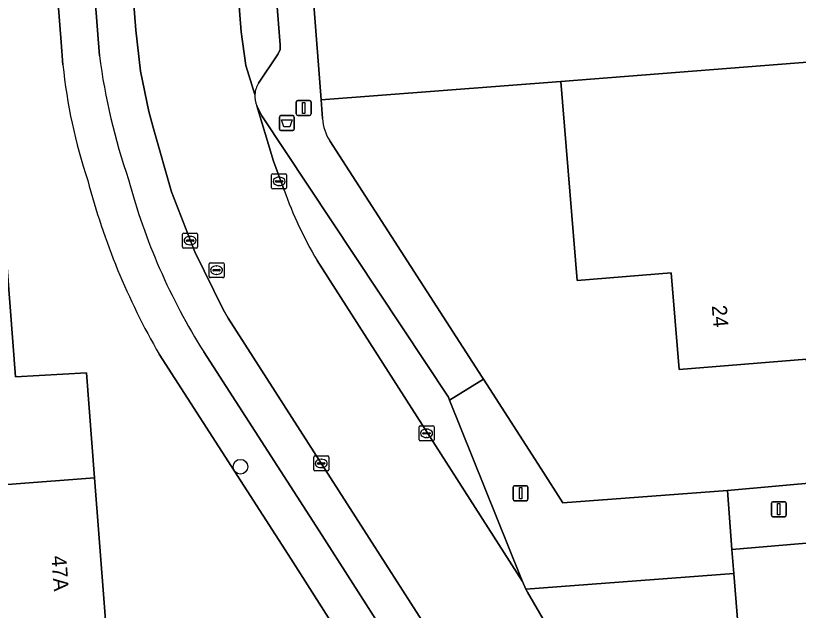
# Model space of a CAD drawing. Extents: x 157793 to 159380, y 380877 to 382313.
# Drawn here: x 158100.7 to 158152.9, y 381310.4 to 381350.1 of the extents above; entities that cross this region are included whole.
import ezdxf

# ---------------------------------------------------------------- set-up
doc = ezdxf.new("R2010")
doc.units = 0
for name, color, linetype in [('IMGEO_Afvalbak', 7, 'Continuous'), ('IMGEO_Boom', 7, 'Continuous'), ('IMGEO_Erf', 7, 'Continuous'), ('IMGEO_Kolk', 7, 'Continuous'), ('IMGEO_Lichtmast', 7, 'Continuous'), ('IMGEO_OVBaan_gesloten', 7, 'Continuous'), ('IMGEO_Pand', 7, 'Continuous'), ('IMGEO_Pand_nummerreeks', 7, 'Continuous'), ('IMGEO_Parkeervlak_open', 7, 'Continuous'), ('IMGEO_Rijbaan_lokaal_gesloten', 7, 'Continuous'), ('IMGEO_Rioolput', 7, 'Continuous'), ('IMGEO_Voetpad_open', 7, 'Continuous')]:
    doc.layers.add(name, color=color, linetype=linetype)

msp = doc.modelspace()

# ---------------------------------------------------------------- linework, layer by layer
at = {"layer": 'IMGEO_Afvalbak'}
for p, q in [((158118.269, 381342.493), (158118.269, 381343.293)), ((158118.269, 381343.293), (158118.269, 381342.493)), ((158118.369, 381343.393), (158119.159, 381343.393)), ((158119.159, 381343.393), (158118.369, 381343.393)), ((158119.259, 381343.293), (158119.259, 381342.493)), ((158119.259, 381342.493), (158119.259, 381343.293)), ((158119.159, 381342.393), (158118.369, 381342.393)), ((158118.369, 381342.393), (158119.159, 381342.393))]:
    msp.add_line(p, q, dxfattribs=at)
msp.add_lwpolyline([(158118.412, 381343.107), (158119.116, 381343.107), (158118.967, 381342.637), (158118.561, 381342.637), (158118.412, 381343.107)], dxfattribs=at)
for centre, start, end in [((158118.369, 381343.293), 90, 180), ((158118.369, 381343.293), 90, 180), ((158119.159, 381343.293), 0, 90), ((158119.159, 381343.293), 360, 90), ((158118.369, 381342.493), 180, 270), ((158118.369, 381342.493), 180, 270), ((158119.159, 381342.493), 270, 0), ((158119.159, 381342.493), 270, 0)]:
    msp.add_arc(centre, 0.1, start, end, dxfattribs=at)
at = {"layer": 'IMGEO_Boom'}
msp.add_circle((158115.672, 381319.964), 0.489, dxfattribs=at)
at = {"layer": 'IMGEO_Erf'}
for points in [[(158103.822, 381346.786), (158103.707, 381348.29), (158103.389, 381352.302), (158102.422, 381364.933), (158097.658, 381364.508), (158099.152, 381345.233), (158100.644, 381325.971), (158105.401, 381326.235), (158105.933, 381319.226), (158106.894, 381306.557), (158066.782, 381303.502), (158066.401, 381308.488), (158065.817, 381316.143), (158063.805, 381342.495), (158062.333, 381361.766), (158060.82, 381381.584), (158095.929, 381384.264), (158100.914, 381384.645), (158100.309, 381392.192)], [(158137.068, 381345.666), (158121.052, 381344.444), (158121.148, 381343.196)], [(158121.637, 381341.71), (158131.815, 381325.934), (158131.903, 381325.796), (158135.738, 381319.823), (158137.196, 381317.545), (158148.179, 381318.378), (158174.322, 381320.744), (158173.998, 381324.728), (158153.786, 381323.086), (158153.466, 381327.148), (158144.954, 381326.456), (158144.428, 381332.904), (158138.148, 381332.392), (158137.068, 381345.666)], [(158136.484, 381250), (158135.122, 381267.156), (158134.745, 381271.897), (158134.324, 381276.911), (158133.427, 381288.599), (158128.577, 381288.152), (158127.803, 381297.075), (158127.997, 381297.125), (158126.787, 381301.809), (158126.593, 381301.759), (158125.087, 381304.314), (158119.05, 381313.79), (158110.244, 381327.475)]]:
    msp.add_lwpolyline(points, dxfattribs=at)
for centre, radius, start, end in [((158138.842, 381350.248), 35.191, 185.645, 198.5212), ((158124.149, 381343.36), 3.006, 183.1301, 213.2997), ((158150.956, 381351.003), 47.022, 194.7024, 210.0241)]:
    msp.add_arc(centre, radius, start, end, dxfattribs=at)
at = {"layer": 'IMGEO_Kolk'}
for p, q in [((158117.753, 381338.58), (158117.753, 381339.432)), ((158117.828, 381339.506), (158118.68, 381339.506)), ((158118.241, 381339.286), (158118.266, 381339.286)), ((158118.754, 381339.432), (158118.754, 381338.58)), ((158118.012, 381339), (158118.012, 381339.012)), ((158118.45, 381338.963), (158118.052, 381338.963)), ((158118.055, 381339.049), (158118.453, 381339.049)), ((158118.264, 381338.726), (158118.239, 381338.726)), ((158118.496, 381339.012), (158118.496, 381339)), ((158118.68, 381338.506), (158117.828, 381338.506)), ((158111.808, 381334.628), (158111.808, 381335.48)), ((158111.883, 381335.554), (158112.735, 381335.554)), ((158112.809, 381335.48), (158112.809, 381334.628)), ((158112.067, 381335.048), (158112.067, 381335.06)), ((158112.505, 381335.011), (158112.107, 381335.011)), ((158112.11, 381335.097), (158112.508, 381335.097)), ((158112.296, 381335.334), (158112.321, 381335.334)), ((158112.551, 381335.06), (158112.551, 381335.048)), ((158112.735, 381334.554), (158111.883, 381334.554)), ((158112.319, 381334.774), (158112.294, 381334.774)), ((158127.592, 381321.767), (158127.592, 381322.619)), ((158127.667, 381322.693), (158128.519, 381322.693)), ((158128.08, 381322.473), (158128.105, 381322.473)), ((158128.593, 381322.619), (158128.593, 381321.767)), ((158127.851, 381322.187), (158127.851, 381322.199)), ((158128.289, 381322.15), (158127.891, 381322.15)), ((158127.894, 381322.236), (158128.292, 381322.236)), ((158128.103, 381321.913), (158128.078, 381321.913)), ((158128.335, 381322.199), (158128.335, 381322.187)), ((158128.519, 381321.693), (158127.667, 381321.693)), ((158120.562, 381319.759), (158120.562, 381320.611)), ((158120.637, 381320.685), (158121.489, 381320.685)), ((158121.05, 381320.465), (158121.075, 381320.465)), ((158121.563, 381320.611), (158121.563, 381319.759)), ((158120.821, 381320.179), (158120.821, 381320.191)), ((158121.259, 381320.142), (158120.861, 381320.142)), ((158120.864, 381320.228), (158121.262, 381320.228)), ((158121.073, 381319.905), (158121.048, 381319.905)), ((158121.305, 381320.191), (158121.305, 381320.179)), ((158121.489, 381319.685), (158120.637, 381319.685))]:
    msp.add_line(p, q, dxfattribs=at)
for points in [[(158117.753, 381338.58), (158117.753, 381339.432)], [(158117.828, 381339.506), (158118.68, 381339.506)], [(158118.754, 381339.432), (158118.754, 381338.58)], [(158118.68, 381338.506), (158117.828, 381338.506)], [(158111.808, 381334.628), (158111.808, 381335.48)], [(158111.883, 381335.554), (158112.735, 381335.554)], [(158112.809, 381335.48), (158112.809, 381334.628)], [(158112.735, 381334.554), (158111.883, 381334.554)], [(158127.592, 381321.767), (158127.592, 381322.619)], [(158127.667, 381322.693), (158128.519, 381322.693)], [(158128.593, 381322.619), (158128.593, 381321.767)], [(158128.519, 381321.693), (158127.667, 381321.693)], [(158120.562, 381319.759), (158120.562, 381320.611)], [(158120.637, 381320.685), (158121.489, 381320.685)], [(158121.563, 381320.611), (158121.563, 381319.759)], [(158121.489, 381319.685), (158120.637, 381319.685)]]:
    msp.add_lwpolyline(points, dxfattribs=at)
for centre, radius, start, end in [((158117.83, 381339.43), 0.0765, 91.552, 178.448), ((158117.83, 381339.43), 0.0765, 91.552, 178.448), ((158118.678, 381339.43), 0.0765, 1.552, 88.448), ((158118.678, 381339.43), 0.0765, 1.552, 88.448), ((158117.83, 381338.582), 0.0765, 181.552, 268.448), ((158117.83, 381338.582), 0.0765, 181.552, 268.448), ((158118.052, 381339.009), 0.0403, 85.8775, 175.7526), ((158118.049, 381338.999), 0.0366, 178.938, 274.7102), ((158118.453, 381339.006), 0.043, 264.8664, 352.4533), ((158118.457, 381339.011), 0.0386, 1.7309, 96.639), ((158118.678, 381338.582), 0.0765, 271.552, 358.448), ((158118.678, 381338.582), 0.0765, 271.552, 358.448), ((158111.885, 381335.478), 0.0765, 91.552, 178.448), ((158111.885, 381335.478), 0.0765, 91.552, 178.448), ((158112.733, 381335.478), 0.0765, 1.552, 88.448), ((158112.733, 381335.478), 0.0765, 1.552, 88.448), ((158112.107, 381335.057), 0.0403, 85.8775, 175.7526), ((158112.104, 381335.047), 0.0366, 178.938, 274.7102), ((158112.508, 381335.054), 0.043, 264.8664, 352.4533), ((158112.512, 381335.059), 0.0386, 1.7309, 96.639), ((158111.885, 381334.63), 0.0765, 181.552, 268.448), ((158111.885, 381334.63), 0.0765, 181.552, 268.448), ((158112.733, 381334.63), 0.0765, 271.552, 358.448), ((158112.733, 381334.63), 0.0765, 271.552, 358.448), ((158127.669, 381322.617), 0.0765, 91.552, 178.448), ((158127.669, 381322.617), 0.0765, 91.552, 178.448), ((158128.517, 381322.617), 0.0765, 1.552, 88.448), ((158128.517, 381322.617), 0.0765, 1.552, 88.448), ((158127.891, 381322.196), 0.0403, 85.8775, 175.7526), ((158127.888, 381322.186), 0.0366, 178.938, 274.7102), ((158128.292, 381322.193), 0.043, 264.8664, 352.4533), ((158128.296, 381322.198), 0.0386, 1.7309, 96.639), ((158127.669, 381321.769), 0.0765, 181.552, 268.448), ((158127.669, 381321.769), 0.0765, 181.552, 268.448), ((158128.517, 381321.769), 0.0765, 271.552, 358.448), ((158128.517, 381321.769), 0.0765, 271.552, 358.448), ((158120.639, 381320.609), 0.0765, 91.552, 178.448), ((158120.639, 381320.609), 0.0765, 91.552, 178.448), ((158121.487, 381320.609), 0.0765, 1.552, 88.448), ((158121.487, 381320.609), 0.0765, 1.552, 88.448), ((158120.639, 381319.761), 0.0765, 181.552, 268.448), ((158120.639, 381319.761), 0.0765, 181.552, 268.448), ((158120.861, 381320.188), 0.0403, 85.8775, 175.7526), ((158120.858, 381320.178), 0.0366, 178.938, 274.7102), ((158121.262, 381320.185), 0.043, 264.8664, 352.4533), ((158121.266, 381320.19), 0.0386, 1.7309, 96.639), ((158121.487, 381319.761), 0.0765, 271.552, 358.448), ((158121.487, 381319.761), 0.0765, 271.552, 358.448)]:
    msp.add_arc(centre, radius, start, end, dxfattribs=at)
for centre, major_axis, ratio, start_param, end_param in [((158118.24, 381339.006), (-0.387, 0.002), 0.722429, 4.712389, 7.853982), ((158118.265, 381339.006), (-0.39, 0.002), 0.717154, 1.570796, 4.712389), ((158112.295, 381335.054), (-0.387, 0.002), 0.722429, 4.712389, 7.853982), ((158112.32, 381335.054), (-0.39, 0.002), 0.717154, 1.570796, 4.712389), ((158128.079, 381322.193), (-0.387, 0.002), 0.722429, 4.712389, 7.853982), ((158128.104, 381322.193), (-0.39, 0.002), 0.717154, 1.570796, 4.712389), ((158121.049, 381320.185), (-0.387, 0.002), 0.722429, 4.712389, 7.853982), ((158121.074, 381320.185), (-0.39, 0.002), 0.717154, 1.570796, 4.712389)]:
    msp.add_ellipse(centre, major_axis=major_axis, ratio=ratio, start_param=start_param, end_param=end_param, dxfattribs=at)
at = {"layer": 'IMGEO_Lichtmast'}
for p, q in [((158119.395, 381343.503), (158119.395, 381344.303)), ((158119.395, 381344.303), (158119.395, 381343.503)), ((158119.495, 381344.403), (158120.285, 381344.403)), ((158120.285, 381344.403), (158119.495, 381344.403)), ((158120.385, 381344.303), (158120.385, 381343.503)), ((158120.385, 381343.503), (158120.385, 381344.303)), ((158120.285, 381343.403), (158119.495, 381343.403)), ((158119.495, 381343.403), (158120.285, 381343.403)), ((158133.975, 381318.693), (158134.765, 381318.693)), ((158134.765, 381318.693), (158133.975, 381318.693)), ((158133.875, 381317.793), (158133.875, 381318.593)), ((158133.875, 381318.593), (158133.875, 381317.793)), ((158134.865, 381318.593), (158134.865, 381317.793)), ((158134.865, 381317.793), (158134.865, 381318.593)), ((158134.765, 381317.693), (158133.975, 381317.693)), ((158133.975, 381317.693), (158134.765, 381317.693)), ((158151.115, 381316.726), (158151.115, 381317.526)), ((158151.115, 381317.526), (158151.115, 381316.726)), ((158151.215, 381317.626), (158152.005, 381317.626)), ((158152.005, 381317.626), (158151.215, 381317.626)), ((158152.105, 381317.526), (158152.105, 381316.726)), ((158152.105, 381316.726), (158152.105, 381317.526)), ((158152.005, 381316.626), (158151.215, 381316.626)), ((158151.215, 381316.626), (158152.005, 381316.626))]:
    msp.add_line(p, q, dxfattribs=at)
for points in [[(158119.815, 381344.278), (158119.965, 381344.278), (158119.965, 381343.528), (158119.815, 381343.528), (158119.815, 381344.278)], [(158134.295, 381318.568), (158134.445, 381318.568), (158134.445, 381317.818), (158134.295, 381317.818), (158134.295, 381318.568)], [(158151.535, 381317.501), (158151.685, 381317.501), (158151.685, 381316.751), (158151.535, 381316.751), (158151.535, 381317.501)]]:
    msp.add_lwpolyline(points, dxfattribs=at)
for centre, start, end in [((158119.495, 381344.303), 90, 180), ((158119.495, 381344.303), 90, 180), ((158120.285, 381344.303), 0, 90), ((158120.285, 381344.303), 360, 90), ((158119.495, 381343.503), 180, 270), ((158119.495, 381343.503), 180, 270), ((158120.285, 381343.503), 270, 0), ((158120.285, 381343.503), 270, 0), ((158133.975, 381318.593), 90, 180), ((158133.975, 381318.593), 90, 180), ((158134.765, 381318.593), 0, 90), ((158134.765, 381318.593), 360, 90), ((158133.975, 381317.793), 180, 270), ((158133.975, 381317.793), 180, 270), ((158134.765, 381317.793), 270, 0), ((158134.765, 381317.793), 270, 0), ((158151.215, 381317.526), 90, 180), ((158151.215, 381317.526), 90, 180), ((158152.005, 381317.526), 0, 90), ((158152.005, 381317.526), 360, 90), ((158151.215, 381316.726), 180, 270), ((158151.215, 381316.726), 180, 270), ((158152.005, 381316.726), 270, 0), ((158152.005, 381316.726), 270, 0)]:
    msp.add_arc(centre, 0.1, start, end, dxfattribs=at)
at = {"layer": 'IMGEO_OVBaan_gesloten'}
for points in [[(158129.628, 381324.416), (158129.552, 381324.607), (158117.104, 381343.377), (158116.771, 381344.039), (158117.878, 381340.348), (158118.578, 381338.424)], [(158120.787, 381333.732), (158134.501, 381312.302), (158134.337, 381312.678), (158129.628, 381324.416)]]:
    msp.add_lwpolyline(points, dxfattribs=at)
msp.add_arc((158144.688, 381347.851), 27.76, 199.8514, 210.5709, dxfattribs=at)
at = {"layer": 'IMGEO_Pand'}
for points in [[(158137.068, 381345.666), (158156.069, 381347.169), (158156.049, 381347.419), (158154.395, 381367.776), (158124.465, 381365.343), (158119.481, 381364.938), (158121.052, 381344.444)], [(158137.068, 381345.666), (158138.148, 381332.392), (158144.428, 381332.904), (158144.954, 381326.456), (158153.466, 381327.148), (158153.786, 381323.086), (158173.998, 381324.728), (158174.322, 381320.744), (158181.702, 381321.344), (158181.297, 381326.328), (158179.429, 381349.319), (158156.049, 381347.419), (158156.069, 381347.169)], [(158065.817, 381316.143), (158105.933, 381319.226), (158105.401, 381326.235), (158100.644, 381325.971), (158099.152, 381345.233), (158063.805, 381342.495)], [(158065.817, 381316.143), (158066.401, 381308.488), (158066.782, 381303.502), (158106.894, 381306.557), (158105.933, 381319.226)], [(158166.317, 381315.953), (158159.212, 381315.351), (158148.478, 381314.442), (158148.612, 381312.832), (158148.658, 381312.275), (158149.209, 381305.365), (158149.969, 381295.114), (158150.013, 381294.53), (158159.691, 381295.356), (158160.857, 381295.455), (158167.979, 381296.063)]]:
    msp.add_lwpolyline(points, close=True, dxfattribs=at)
at = {"layer": 'IMGEO_Parkeervlak_open'}
for points in [[(158068.546, 381497.113), (158089.726, 381454.684), (158103.399, 381426.613), (158104.154, 381425.047), (158107.132, 381417.89), (158109.46, 381410.496), (158111.117, 381402.923), (158112.092, 381395.233), (158115.709, 381348.982), (158116.021, 381346.737), (158116.632, 381344.813)], [(158133.891, 381298.949), (158130.692, 381305.062), (158129.631, 381306.832), (158114.85, 381329.868), (158114.523, 381330.452), (158112.621, 381334.306), (158111.071, 381338.314), (158109.885, 381342.445), (158109.545, 381343.679), (158108.99, 381346.367), (158108.678, 381349.094), (158105.079, 381395.169), (158104.129, 381402.425), (158102.534, 381409.567), (158100.308, 381416.538), (158097.468, 381423.282), (158097, 381424.252), (158084.358, 381449.773), (158063.323, 381491.963)], [(158101.929, 381399.96), (158102.313, 381397.022), (158102.595, 381394.475), (158103.917, 381377.783), (158105.807, 381353.112), (158106.254, 381347.389)], [(158116.881, 381345.559), (158118.198, 381347.518), (158118.311, 381347.813), (158118.332, 381348.113), (158117.089, 381363.572), (158116.447, 381371.8), (158115.605, 381383.267), (158114.643, 381395.603)], [(158113.218, 381327.629), (158120.925, 381315.694), (158127.67, 381305.131), (158128.695, 381303.42), (158129.87, 381301.272)]]:
    msp.add_lwpolyline(points, dxfattribs=at)
for centre, radius, start, end in [((158148.295, 381352.916), 42.403, 187.4897, 198.9859), ((158118.225, 381344.696), 1.597, 147.2862, 175.7978), ((158148.404, 381349.838), 41.608, 194.9257, 212.2598)]:
    msp.add_arc(centre, radius, start, end, dxfattribs=at)
at = {"layer": 'IMGEO_Rijbaan_lokaal_gesloten'}
for points in [[(158116.632, 381344.813), (158116.021, 381346.737), (158115.709, 381348.982), (158112.092, 381395.233), (158111.117, 381402.923), (158109.46, 381410.496), (158107.132, 381417.89), (158104.154, 381425.047), (158103.399, 381426.613), (158089.726, 381454.684), (158068.546, 381497.113), (158067.74, 381498.783), (158049.539, 381535.45)], [(158105.079, 381395.169), (158108.678, 381349.094), (158108.99, 381346.367), (158109.545, 381343.679), (158109.885, 381342.445), (158111.071, 381338.314), (158112.621, 381334.306), (158114.523, 381330.452), (158114.85, 381329.868), (158129.631, 381306.832), (158130.692, 381305.062), (158133.891, 381298.949), (158135.117, 381296.291), (158136.795, 381291.831), (158138.068, 381287.238), (158138.925, 381282.55), (158138.944, 381282.307), (158138.872, 381280.436), (158142.335, 381241.215)], [(158118.578, 381338.424), (158117.878, 381340.348), (158116.771, 381344.039)], [(158148.225, 381253.262), (158146.678, 381273.28), (158145.948, 381282.137), (158145.324, 381286.667), (158144.297, 381291.124), (158143.195, 381294.604), (158139.003, 381304.419), (158134.841, 381311.603), (158134.72, 381311.792), (158134.501, 381312.302), (158120.787, 381333.732)]]:
    msp.add_lwpolyline(points, dxfattribs=at)
for centre, radius, start, end in [((158118.22, 381344.699), 1.592, 175.8798, 204.4822), ((158144.688, 381347.851), 27.76, 199.8514, 210.5709)]:
    msp.add_arc(centre, radius, start, end, dxfattribs=at)
at = {"layer": 'IMGEO_Rioolput'}
for p, q in [((158113.571, 381332.654), (158113.571, 381333.506)), ((158113.646, 381333.58), (158114.498, 381333.58)), ((158114.059, 381333.36), (158114.084, 381333.36)), ((158114.572, 381333.506), (158114.572, 381332.654)), ((158113.83, 381333.074), (158113.83, 381333.086)), ((158114.268, 381333.037), (158113.87, 381333.037)), ((158113.873, 381333.123), (158114.271, 381333.123)), ((158114.082, 381332.8), (158114.057, 381332.8)), ((158114.314, 381333.086), (158114.314, 381333.074)), ((158114.498, 381332.58), (158113.646, 381332.58))]:
    msp.add_line(p, q, dxfattribs=at)
for points in [[(158113.571, 381332.654), (158113.571, 381333.506)], [(158113.646, 381333.58), (158114.498, 381333.58)], [(158114.572, 381333.506), (158114.572, 381332.654)], [(158114.498, 381332.58), (158113.646, 381332.58)]]:
    msp.add_lwpolyline(points, dxfattribs=at)
for centre, radius, start, end in [((158113.648, 381333.504), 0.0765, 91.552, 178.448), ((158113.648, 381333.504), 0.0765, 91.552, 178.448), ((158114.496, 381333.504), 0.0765, 1.552, 88.448), ((158114.496, 381333.504), 0.0765, 1.552, 88.448), ((158113.87, 381333.083), 0.0403, 85.8775, 175.7526), ((158113.867, 381333.073), 0.0366, 178.938, 274.7102), ((158114.271, 381333.08), 0.043, 264.8664, 352.4533), ((158114.275, 381333.085), 0.0386, 1.7309, 96.639), ((158113.648, 381332.656), 0.0765, 181.552, 268.448), ((158113.648, 381332.656), 0.0765, 181.552, 268.448), ((158114.496, 381332.656), 0.0765, 271.552, 358.448), ((158114.496, 381332.656), 0.0765, 271.552, 358.448)]:
    msp.add_arc(centre, radius, start, end, dxfattribs=at)
for centre, major_axis, ratio, start_param, end_param in [((158114.058, 381333.08), (-0.387, 0.002), 0.722429, 4.712389, 7.853982), ((158114.083, 381333.08), (-0.39, 0.002), 0.717154, 1.570796, 4.712389)]:
    msp.add_ellipse(centre, major_axis=major_axis, ratio=ratio, start_param=start_param, end_param=end_param, dxfattribs=at)
at = {"layer": 'IMGEO_Voetpad_open'}
for points in [[(158061.531, 381483.298), (158062.259, 381482.737), (158062.447, 381482.359), (158067.697, 381471.8), (158067.864, 381471.463), (158067.97, 381471.251), (158070.869, 381465.451), (158071.21, 381464.76), (158072.051, 381463.055), (158083.681, 381440.171), (158086.434, 381434.52), (158092.346, 381422.615), (158094.422, 381418.152), (158096.796, 381411.807), (158098.594, 381405.276), (158099.801, 381398.61), (158100.156, 381394.103), (158100.309, 381392.192), (158100.914, 381384.645), (158101.404, 381378.242), (158102.422, 381364.933), (158103.389, 381352.302), (158103.707, 381348.29), (158103.822, 381346.786)], [(158106.254, 381347.389), (158105.807, 381353.112), (158103.917, 381377.783), (158102.595, 381394.475), (158102.313, 381397.022), (158101.929, 381399.96)], [(158114.643, 381395.603), (158115.605, 381383.267), (158116.447, 381371.8), (158117.089, 381363.572), (158118.332, 381348.113), (158118.311, 381347.813), (158118.198, 381347.518), (158116.881, 381345.559)], [(158121.148, 381343.196), (158121.052, 381344.444), (158119.481, 381364.938)], [(158116.771, 381344.039), (158117.104, 381343.377), (158129.552, 381324.607), (158129.628, 381324.416), (158131.903, 381325.796), (158131.815, 381325.934), (158121.637, 381341.71)], [(158129.87, 381301.272), (158128.695, 381303.42), (158127.67, 381305.131), (158120.925, 381315.694), (158113.218, 381327.629)], [(158110.244, 381327.475), (158119.05, 381313.79), (158125.087, 381304.314), (158126.593, 381301.759), (158126.787, 381301.809), (158127.997, 381297.125), (158127.803, 381297.075), (158128.577, 381288.152), (158133.427, 381288.599), (158134.324, 381276.911), (158134.745, 381271.897), (158135.122, 381267.156), (158137.665, 381267.241), (158138.872, 381280.436), (158138.944, 381282.307), (158138.925, 381282.55), (158138.068, 381287.238), (158136.795, 381291.831), (158135.117, 381296.291), (158133.891, 381298.949)]]:
    msp.add_lwpolyline(points, dxfattribs=at)
for points in [[(158148.179, 381318.378), (158137.196, 381317.545), (158135.738, 381319.823), (158131.903, 381325.796), (158129.628, 381324.416), (158134.337, 381312.678), (158134.501, 381312.302), (158134.72, 381311.792), (158148.612, 381312.832), (158148.478, 381314.442)], [(158200.897, 381318.677), (158200.589, 381322.782), (158181.702, 381321.344), (158174.322, 381320.744), (158148.179, 381318.378), (158148.478, 381314.442), (158159.212, 381315.351), (158166.317, 381315.953), (158173.112, 381316.529), (158178.098, 381316.915), (158184.505, 381317.435), (158192.346, 381318.048)], [(158148.658, 381312.275), (158148.612, 381312.832), (158134.72, 381311.792), (158134.841, 381311.603), (158139.003, 381304.419), (158143.195, 381294.604), (158149.969, 381295.114), (158149.209, 381305.365)]]:
    msp.add_lwpolyline(points, close=True, dxfattribs=at)
for centre, radius, start, end in [((158148.295, 381352.916), 42.403, 187.4897, 198.9859), ((158138.842, 381350.248), 35.191, 185.645, 198.5212), ((158118.225, 381344.696), 1.597, 147.2862, 175.7978), ((158118.22, 381344.699), 1.592, 175.8798, 204.4822), ((158124.149, 381343.36), 3.006, 183.1301, 213.2997), ((158150.956, 381351.003), 47.022, 194.7024, 210.0241), ((158148.404, 381349.838), 41.608, 194.9257, 212.2598)]:
    msp.add_arc(centre, radius, start, end, dxfattribs=at)

# ---------------------------------------------------------------- texts
at = {"layer": 'IMGEO_Pand_nummerreeks'}
for s, rotation, p in [('24', 274.6636, (158147.135, 381330.709)), ('47A', 274.3378, (158103.04, 381313.995))]:
    msp.add_text(s, height=1, rotation=rotation, dxfattribs=at).set_placement(p)

doc.saveas('drawing.dxf')
